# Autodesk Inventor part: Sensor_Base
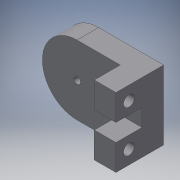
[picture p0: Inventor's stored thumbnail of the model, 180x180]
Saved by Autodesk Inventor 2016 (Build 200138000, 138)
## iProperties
Created: 2016-07
Part Number: Sensor_Base
Material: Generic
Document SubType Name: Modeling
Designer: jose
Density: 1 g/cm^3
Appearance: Default
Author: jose
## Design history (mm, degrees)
sketch "Sketch1"
  geometry: L1 (0, 10.16)-(19.05, 10.16); L2 (19.05, 10.16)-(19.05, -10.16); L3 (19.05, -10.16)-(0, -10.16); C1 r 3.086 at (0, 0); A1 r 10.16 centre (0, 0) between (0, 10.16) and (0, -10.16); 1 further point
  constraints: 6 end point, 2 centre point, 2 coincident, 2 point on circle, 2 tangent, 1 horizontal, 1 parallel, 1 perpendicular
  dimensions: "d0" = 6.1722 diameter of C1; "d1" = 20.32 diameter of A1; "d2" = 19.05 distance from line of point (0, 0) L2
extrude "Extrusion1" new body sketch "Sketch1" distance "d3" = 6.35; taper "d4" = 0 deg
extrude "Extrusion2" cut sketch "Sketch1" distance "d5" = 3.429; taper "d6" = 0 deg
sketch "Sketch2"
  geometry: L1 (19.05, -10.16)-(19.05, 10.16) reference; L2 (19.05, 10.16)-(12.7, 10.16); L3 (12.7, 10.16)-(12.7, -10.16); L4 (12.7, -10.16)-(19.05, -10.16); L5 (19.05, -10.16)-(19.05, 10.16); L6 (0, -10.16)-(19.05, -10.16) reference; 1 further point
  constraints: 8 end point, 2 parallel, 1 collinear, 1 horizontal, 1 perpendicular
  dimensions: "d7" = 6.35 distance between parallel lines of L1 L3
extrude "Extrusion3" join sketch "Sketch2" distance "d8" = 7.62; taper "d9" = 0 deg
sketch "Sketch4"
  geometry: L1 (7.526, 12.065)-(-6.35, 12.065); L2 (7.62, 14.605)-(0, 14.605); L3 (0, 14.605)-(0, 9.525); L4 (0, 9.525)-(7.62, 9.525); L5 (7.62, 9.525)-(7.62, 14.605); L6 (7.62, 22.225)-(7.62, 1.905) reference; L7 (0, 1.905)-(0, 22.225) reference
  constraints: 10 end point, 2 collinear, 2 horizontal, 2 parallel, 1 perpendicular, 1 other
  dimensions: "d12" = 5.08 distance between parallel lines of L4 L2
extrude "Extrusion5" cut sketch "Sketch4" stored distance "d13" = 6.35; taper "d14" = 0 deg
sketch "Sketch5"
  geometry: L1 (-6.35, 12.7)-(-6.35, 7.62) reference; L2 (-6.35, 10.16)-(0, 10.16); L3 (-6.35, 12.7)-(-13.97, 12.7) reference; L4 (-10.16, 12.7)-(-10.16, 19.863); L5 (-10.16, 12.7)-(-10.16, -1.284); C1 r 1.588 at (-10.16, 4.039); C2 r 1.588 at (-10.16, 16.281); 1 further point
  constraints: 6 end point, 3 midpoint, 2 centre point, 2 vertical, 1 coincident, 1 horizontal, 1 point on line
  dimensions: "d21" = 3.175 diameter of C1; "d22" = 3.175 diameter of C2; "d30" = 12.2428 distance of C1.centre C2.centre; "d31" = 6.1214 distance from line of L2 C1.centre
extrude "Extrusion6" cut sketch "Sketch5" stored distance "d25" = 25.4; taper "d26" = 0 deg
sketch "Sketch6"
  geometry: C1 r 1.016 at (0, 0); 1 further point
  constraints: 1 centre point, 1 coincident
  dimensions: "d27" = 2.032 diameter of C1
extrude "Extrusion7" cut sketch "Sketch6" stored distance "d28" = 25.4; taper "d29" = 0 deg
body "Solid1"
